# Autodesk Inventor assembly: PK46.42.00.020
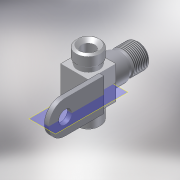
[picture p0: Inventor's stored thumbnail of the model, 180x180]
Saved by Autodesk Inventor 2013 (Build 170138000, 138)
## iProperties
Created: 2005-06
Part Number: PK46.42.00.020
Document SubType Name: Assembly
Designer: salex
Manufacturer: Standard
Standards Organization: Custom
Author: salex
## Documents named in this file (4)
- C:\Product Design Suite 2013 Test Drive\Dynamic Simulation\Workspace\Assy, Chassis, Front\PK46.42.00.020.iam
- C:\Product Design Suite 2013 Test Drive\Dynamic Simulation\Workspace\Assy, Chassis, Front\PK46.42.00.021.ipt
- C:\Product Design Suite 2013 Test Drive\Dynamic Simulation\Workspace\Assy, Chassis, Front\PK46.42.00.022.ipt
- C:\Product Design Suite 2013 Test Drive\Dynamic Simulation\Workspace\Assy, Chassis, Front\027.03.01.012.ipt
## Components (3 placed, 3 different names)
1. PK46.42.00.021:1 — Вставка:1, Заподлицо:1, Совмещение:2, Совмещение:3
2. PK46.42.00.022:1 — Заподлицо:1, Совмещение:2, Совмещение:3
3. 027.03.01.012:1 — Вставка:1
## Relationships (4: Mate 2, Insert 1, Flush 1)
- Вставка:1 [Insert]: PK46.42.00.021:1 ↔ 027.03.01.012:1
- Заподлицо:1 [Flush]: PK46.42.00.021:1 ↔ PK46.42.00.022:1
- Совмещение:2 [Mate]: PK46.42.00.021:1 ↔ PK46.42.00.022:1
- Совмещение:3 [Mate]: PK46.42.00.021:1 ↔ PK46.42.00.022:1
